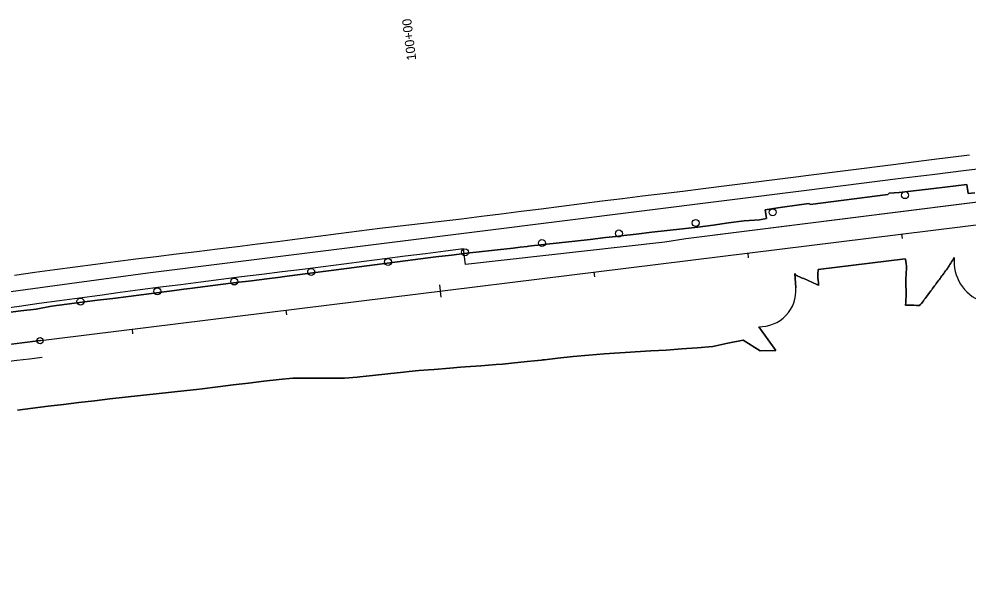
# Model space of a CAD drawing. Extents: x 1568809 to 1572786, y 728326 to 734907.
# Drawn here: x 1570015 to 1570627, y 731986 to 732358 of the extents above; entities that cross this region are included whole.
import ezdxf

# ---------------------------------------------------------------- set-up
doc = ezdxf.new("R2010")
doc.units = 0
for name, color, linetype in [('R_Horz Alg', 7, 'Continuous'), ('R_Horz Alg Annot', 7, 'Continuous'), ('R_MOT', 7, 'Continuous'), ('R_No Plot', 7, 'Continuous'), ('R_Proposed Const Limits_Fill', 7, 'Continuous'), ('R_Striping', 7, 'Continuous')]:
    doc.layers.add(name, color=color, linetype=linetype)

msp = doc.modelspace()

# ---------------------------------------------------------------- linework, layer by layer
at = {"layer": 'R_Horz Alg'}
msp.add_line((1569774.69, 732119.01), (1571082.41, 732280.73), dxfattribs=at)
msp.add_arc((1570379.97, 729307.25), 2864.79, 97.05, 102.33591, dxfattribs=at)
at = {"layer": 'R_Horz Alg Annot'}
msp.add_line((1569897.12, 732134.15), (1570028.36, 732150.38), dxfattribs=at)
for points in [[(1570584.5, 732216.13), (1570584.13, 732219.11)], [(1570485.25, 732203.86), (1570484.88, 732206.84)], [(1570386.01, 732191.59), (1570385.64, 732194.56)], [(1570285.91, 732186.26), (1570286.89, 732178.32)], [(1570187.52, 732167.04), (1570187.15, 732170.02)], [(1570088.28, 732154.77), (1570087.91, 732157.74)]]:
    msp.add_lwpolyline(points, dxfattribs=at)
msp.add_circle((1570028.36, 732150.38), 2, dxfattribs=at)
at = {"layer": 'R_MOT'}
for centre in [(1570586.12, 732244.2), (1570500.72, 732233.17), (1570451.19, 732226.24), (1570401.63, 732219.47), (1570352, 732213.28), (1570302.37, 732207.36), (1570252.77, 732201.07), (1570203.17, 732194.71), (1570153.56, 732188.5), (1570103.96, 732182.17), (1570054.42, 732175.57)]:
    msp.add_circle(centre, 2.25, dxfattribs=at)
at = {"layer": 'R_No Plot'}
for p, q in [((1570625.95, 732250.99), (1570626.75, 732245.23)), ((1570626.75, 732245.23), (1570625.95, 732250.99)), ((1570496.73, 732229.18), (1570495.95, 732234.82)), ((1570495.95, 732234.82), (1570496.73, 732229.18)), ((1570302.77, 732199.43), (1570301.51, 732209.57)), ((1570302.77, 732199.43), (1570301.51, 732209.57)), ((1570586.31, 732203.09), (1570530.21, 732196.15)), ((1570530.21, 732196.15), (1570586.31, 732203.09)), ((1570515.16, 732193.67), (1570515.78, 732184.45)), ((1570515.78, 732184.45), (1570515.16, 732193.67)), ((1570491.78, 732159.29), (1570502.74, 732143.97)), ((1570502.74, 732143.97), (1570491.78, 732159.29))]:
    msp.add_line(p, q, dxfattribs=at)
for points in [[(1571080.52, 732296.05), (1570444.72, 732215.92), (1570431.22, 732213.94), (1570302.77, 732199.43)], [(1571080.52, 732296.05), (1570973.02, 732293.44), (1570943.63, 732289.39), (1570933.75, 732279.73), (1570896.54, 732272.86), (1570444.72, 732215.92), (1570431.22, 732213.94), (1570302.77, 732199.43)], [(1570524.31, 732238.82), (1570524.95, 732238.13), (1570574.94, 732244.65), (1570575.94, 732245.46)], [(1570575.94, 732245.46), (1570574.94, 732244.65), (1570524.95, 732238.13), (1570524.31, 732238.82)], [(1570575.94, 732245.46), (1570582.24, 732245.98), (1570604.61, 732248.54), (1570625.95, 732250.99)], [(1570625.95, 732250.99), (1570604.61, 732248.54), (1570582.24, 732245.98), (1570575.94, 732245.46)], [(1570626.75, 732245.23), (1570631.21, 732245.78)], [(1570631.21, 732245.78), (1570626.75, 732245.23)], [(1570495.95, 732234.82), (1570504.17, 732235.97), (1570519.32, 732238.1), (1570524.31, 732238.82)], [(1570524.31, 732238.82), (1570519.32, 732238.1), (1570504.17, 732235.97), (1570495.95, 732234.82)], [(1570005.99, 732168.34), (1570015.92, 732169.51), (1570025.85, 732170.67), (1570035.69, 732172.64), (1570045.61, 732173.86), (1570055.53, 732175.11), (1570065.45, 732176.38), (1570075.37, 732177.64), (1570085.29, 732178.92), (1570095.21, 732180.22), (1570105.13, 732181.48), (1570115.05, 732182.74), (1570121.14, 732183.54), (1570124.96, 732184.05), (1570134.88, 732185.29), (1570144.8, 732186.57), (1570154.73, 732187.8), (1570164.65, 732189.03), (1570174.57, 732190.26), (1570183.36, 732191.36), (1570184.5, 732191.5), (1570194.42, 732192.73), (1570204.33, 732194.04), (1570214.25, 732195.35), (1570216.08, 732195.6), (1570224.16, 732196.65), (1570226, 732196.9), (1570234.08, 732197.96), (1570243.99, 732199.27), (1570253.91, 732200.56), (1570263.83, 732201.85), (1570273.74, 732203.15), (1570283.66, 732204.45), (1570293.59, 732205.59), (1570303.53, 732206.73), (1570313.47, 732207.83), (1570317.43, 732208.28), (1570323.41, 732208.94), (1570333.34, 732210.07), (1570337.9, 732210.58), (1570342.55, 732211.11), (1570343.28, 732211.19), (1570353.22, 732212.32), (1570363.15, 732213.44), (1570373.1, 732214.53), (1570383.03, 732215.66), (1570392.97, 732216.79), (1570399.78, 732217.56), (1570402.91, 732217.91), (1570412.84, 732219.08), (1570422.77, 732220.22), (1570432.71, 732221.35), (1570442.65, 732222.48), (1570452.58, 732223.59), (1570462.51, 732224.81), (1570472.39, 732226.37), (1570482.32, 732227.56), (1570492.32, 732228.23), (1570496.73, 732229.18)], [(1570496.73, 732229.18), (1570492.32, 732228.23), (1570482.32, 732227.56), (1570472.39, 732226.37), (1570462.51, 732224.81), (1570452.58, 732223.59), (1570442.65, 732222.48), (1570432.71, 732221.35), (1570422.77, 732220.22), (1570412.84, 732219.08), (1570402.91, 732217.91), (1570399.78, 732217.56), (1570392.97, 732216.79), (1570383.03, 732215.66), (1570373.1, 732214.53), (1570363.15, 732213.44), (1570353.22, 732212.32), (1570343.28, 732211.19), (1570342.55, 732211.11), (1570337.9, 732210.58), (1570333.34, 732210.07), (1570323.41, 732208.94), (1570317.43, 732208.28), (1570313.47, 732207.83), (1570303.53, 732206.73), (1570293.59, 732205.59), (1570283.66, 732204.45), (1570273.74, 732203.15), (1570263.83, 732201.85), (1570253.91, 732200.56), (1570243.99, 732199.27), (1570234.08, 732197.96), (1570226, 732196.9), (1570224.16, 732196.65), (1570216.08, 732195.6), (1570214.25, 732195.35), (1570204.33, 732194.04), (1570194.42, 732192.73), (1570184.5, 732191.5), (1570183.36, 732191.36), (1570174.57, 732190.26), (1570164.65, 732189.03), (1570154.73, 732187.8), (1570144.8, 732186.57), (1570134.88, 732185.29), (1570124.96, 732184.05), (1570121.14, 732183.54), (1570115.05, 732182.74), (1570105.13, 732181.48), (1570095.21, 732180.22), (1570085.29, 732178.92), (1570075.37, 732177.64), (1570065.45, 732176.38), (1570055.53, 732175.11), (1570045.61, 732173.86), (1570035.69, 732172.64), (1570025.85, 732170.67), (1570015.92, 732169.51), (1570005.99, 732168.34)], [(1570301.51, 732209.57), (1570289.87, 732208.1), (1570276.82, 732206.44), (1570263.78, 732204.79), (1570250.74, 732203.13), (1570237.44, 732201.43), (1570224.14, 732199.72), (1570210.85, 732198.02), (1570197.55, 732196.32), (1570184.46, 732194.68), (1570171.36, 732193.05), (1570158.27, 732191.41), (1570145.18, 732189.78), (1570132.12, 732188.11), (1570119.06, 732186.43), (1570106, 732184.76), (1570092.95, 732183.09), (1570079.91, 732181.33), (1570066.88, 732179.57), (1570053.85, 732177.81), (1570040.82, 732176.05), (1570027.86, 732174.24), (1570014.9, 732172.44), (1570001.94, 732170.63)], [(1570301.51, 732209.57), (1570289.87, 732208.1), (1570276.82, 732206.44), (1570263.78, 732204.79), (1570250.74, 732203.13), (1570237.44, 732201.43), (1570224.14, 732199.72), (1570210.85, 732198.02), (1570197.55, 732196.32), (1570184.46, 732194.68), (1570171.36, 732193.05), (1570158.27, 732191.41), (1570145.18, 732189.78), (1570132.12, 732188.11), (1570119.06, 732186.43), (1570106, 732184.76), (1570092.95, 732183.09), (1570079.91, 732181.33), (1570066.88, 732179.57), (1570053.85, 732177.81), (1570040.82, 732176.05), (1570027.86, 732174.24), (1570014.9, 732172.44), (1570001.94, 732170.63)], [(1570586.45, 732173.28), (1570586.47, 732173.55), (1570586.56, 732174.75), (1570586.65, 732175.94), (1570586.74, 732177.14), (1570586.83, 732178.34), (1570586.92, 732179.53), (1570586.89, 732180.83), (1570586.84, 732182.13), (1570586.79, 732183.44), (1570586.74, 732184.75), (1570586.69, 732186.05), (1570586.65, 732187.36), (1570586.6, 732188.67), (1570586.6, 732189.93), (1570586.69, 732191.13), (1570586.78, 732192.33), (1570586.87, 732193.53), (1570586.96, 732194.73), (1570587.04, 732195.93), (1570587.13, 732197.12), (1570586.97, 732198.52), (1570586.77, 732199.95), (1570586.56, 732201.38), (1570586.35, 732202.81), (1570586.31, 732203.09)], [(1570586.31, 732203.09), (1570586.35, 732202.81), (1570586.56, 732201.38), (1570586.77, 732199.95), (1570586.97, 732198.52), (1570587.13, 732197.12), (1570587.04, 732195.93), (1570586.96, 732194.73), (1570586.87, 732193.53), (1570586.78, 732192.33), (1570586.69, 732191.13), (1570586.6, 732189.93), (1570586.6, 732188.67), (1570586.65, 732187.36), (1570586.69, 732186.05), (1570586.74, 732184.75), (1570586.79, 732183.44), (1570586.84, 732182.13), (1570586.89, 732180.83), (1570586.92, 732179.53), (1570586.83, 732178.34), (1570586.74, 732177.14), (1570586.65, 732175.94), (1570586.56, 732174.75), (1570586.47, 732173.55), (1570586.45, 732173.28)], [(1570617.86, 732203.94), (1570616.67, 732201.99), (1570616.15, 732201.13), (1570615.62, 732200.27), (1570615.1, 732199.41), (1570614.58, 732198.55), (1570614.04, 732197.7), (1570613.44, 732196.9), (1570612.85, 732196.09), (1570612.25, 732195.29), (1570611.66, 732194.48), (1570611.07, 732193.68), (1570610.47, 732192.87), (1570609.88, 732192.07), (1570609.28, 732191.26), (1570608.69, 732190.46), (1570608.09, 732189.66), (1570607.5, 732188.85), (1570606.9, 732188.05), (1570606.31, 732187.24), (1570605.72, 732186.44), (1570605.12, 732185.63), (1570604.52, 732184.83), (1570603.93, 732184.03), (1570603.33, 732183.22), (1570602.73, 732182.42), (1570602.14, 732181.62), (1570601.54, 732180.82), (1570600.94, 732180.01), (1570600.35, 732179.21), (1570599.76, 732178.4), (1570599.16, 732177.6), (1570598.57, 732176.79), (1570597.98, 732175.98), (1570597.39, 732175.18), (1570596.79, 732174.37), (1570596.2, 732173.57), (1570595.21, 732173.07), (1570593.54, 732173.11), (1570591.86, 732173.15), (1570590.18, 732173.19), (1570588.51, 732173.23), (1570586.83, 732173.27), (1570586.45, 732173.28)], [(1570586.45, 732173.28), (1570586.83, 732173.27), (1570588.51, 732173.23), (1570590.18, 732173.19), (1570591.86, 732173.15), (1570593.54, 732173.11), (1570595.21, 732173.07), (1570596.2, 732173.57), (1570596.79, 732174.37), (1570597.39, 732175.18), (1570597.98, 732175.98), (1570598.57, 732176.79), (1570599.16, 732177.6), (1570599.76, 732178.4), (1570600.35, 732179.21), (1570600.94, 732180.01), (1570601.54, 732180.82), (1570602.14, 732181.62), (1570602.73, 732182.42), (1570603.33, 732183.22), (1570603.93, 732184.03), (1570604.52, 732184.83), (1570605.12, 732185.63), (1570605.72, 732186.44), (1570606.31, 732187.24), (1570606.9, 732188.05), (1570607.5, 732188.85), (1570608.09, 732189.66), (1570608.69, 732190.46), (1570609.28, 732191.26), (1570609.88, 732192.07), (1570610.47, 732192.87), (1570611.07, 732193.68), (1570611.66, 732194.48), (1570612.25, 732195.29), (1570612.85, 732196.09), (1570613.44, 732196.9), (1570614.04, 732197.7), (1570614.58, 732198.55), (1570615.1, 732199.41), (1570615.62, 732200.27), (1570616.15, 732201.13), (1570616.67, 732201.99), (1570617.86, 732203.94)], [(1570530.21, 732196.15), (1570530.15, 732195.78), (1570529.84, 732193.74), (1570529.83, 732192.11), (1570529.97, 732190.66), (1570530.11, 732189.21), (1570530.24, 732187.76), (1570530.38, 732186.3), (1570530.4, 732186)], [(1570530.4, 732186), (1570530.38, 732186.3), (1570530.24, 732187.76), (1570530.11, 732189.21), (1570529.97, 732190.66), (1570529.83, 732192.11), (1570529.84, 732193.74), (1570530.15, 732195.78), (1570530.21, 732196.15)], [(1570530.4, 732186), (1570530.21, 732186.09), (1570529.27, 732186.51), (1570528.33, 732186.94), (1570527.4, 732187.36), (1570526.46, 732187.78), (1570525.52, 732188.21), (1570524.58, 732188.63), (1570523.65, 732189.06), (1570522.71, 732189.48), (1570521.77, 732189.9), (1570520.83, 732190.33), (1570519.9, 732190.75), (1570518.96, 732191.17), (1570518.02, 732191.6), (1570517.08, 732191.96), (1570516.78, 732192.08), (1570516.49, 732192.24), (1570516.21, 732192.43), (1570515.94, 732192.65), (1570515.68, 732192.9), (1570515.45, 732193.18), (1570515.25, 732193.49), (1570515.16, 732193.67)], [(1570515.16, 732193.67), (1570515.25, 732193.49), (1570515.45, 732193.18), (1570515.68, 732192.9), (1570515.94, 732192.65), (1570516.21, 732192.43), (1570516.49, 732192.24), (1570516.78, 732192.08), (1570517.08, 732191.96), (1570518.02, 732191.6), (1570518.96, 732191.17), (1570519.9, 732190.75), (1570520.83, 732190.33), (1570521.77, 732189.9), (1570522.71, 732189.48), (1570523.65, 732189.06), (1570524.58, 732188.63), (1570525.52, 732188.21), (1570526.46, 732187.78), (1570527.4, 732187.36), (1570528.33, 732186.94), (1570529.27, 732186.51), (1570530.21, 732186.09), (1570530.4, 732186)], [(1570502.74, 732143.97), (1570492.69, 732143.73), (1570481.76, 732150.66), (1570471.92, 732148.74), (1570462.1, 732146.65), (1570452.15, 732145.61), (1570442.15, 732144.99), (1570432.16, 732144.3), (1570422.16, 732143.71), (1570412.16, 732143.12), (1570409, 732142.94), (1570402.16, 732142.48), (1570392.16, 732141.82), (1570382.2, 732140.92), (1570372.23, 732140.04), (1570362.29, 732138.98), (1570353.68, 732138.06), (1570352.34, 732137.91), (1570351.61, 732137.84), (1570346.95, 732137.34), (1570342.4, 732136.85), (1570332.44, 732135.91), (1570326.46, 732135.27), (1570322.48, 732134.94), (1570312.5, 732134.19), (1570309.36, 732133.93), (1570302.52, 732133.42), (1570299.37, 732133.18), (1570292.53, 732132.66), (1570282.57, 732131.78), (1570278.92, 732131.51), (1570272.58, 732131.05), (1570266.46, 732130.4), (1570262.64, 732129.99), (1570252.69, 732128.93), (1570242.74, 732127.95), (1570234.63, 732127.1), (1570232.8, 732126.85), (1570224.67, 732126.14), (1570222.8, 732126.18), (1570212.72, 732126.23), (1570202.64, 732126.24), (1570192.57, 732126.23), (1570191.41, 732126.23), (1570182.61, 732125.29), (1570172.66, 732124.21), (1570162.74, 732123.03), (1570152.81, 732121.8), (1570142.89, 732120.58), (1570132.96, 732119.35), (1570129.13, 732118.94), (1570123.03, 732118.18), (1570113.08, 732117.13), (1570103.14, 732116.06), (1570093.2, 732115), (1570083.26, 732113.89), (1570073.32, 732112.77), (1570063.38, 732111.62), (1570053.45, 732110.45), (1570043.52, 732109.27), (1570033.6, 732108.05), (1570023.67, 732106.82), (1570013.75, 732105.61)], [(1570013.75, 732105.61), (1570023.67, 732106.82), (1570033.6, 732108.05), (1570043.52, 732109.27), (1570053.45, 732110.45), (1570063.38, 732111.62), (1570073.32, 732112.77), (1570083.26, 732113.89), (1570093.2, 732115), (1570103.14, 732116.06), (1570113.08, 732117.13), (1570123.03, 732118.18), (1570129.13, 732118.94), (1570132.96, 732119.35), (1570142.89, 732120.58), (1570152.81, 732121.8), (1570162.74, 732123.03), (1570172.66, 732124.21), (1570182.61, 732125.29), (1570191.41, 732126.23), (1570192.57, 732126.23), (1570202.64, 732126.24), (1570212.72, 732126.23), (1570222.8, 732126.18), (1570224.67, 732126.14), (1570232.8, 732126.85), (1570234.63, 732127.1), (1570242.74, 732127.95), (1570252.69, 732128.93), (1570262.64, 732129.99), (1570266.46, 732130.4), (1570272.58, 732131.05), (1570278.92, 732131.51), (1570282.57, 732131.78), (1570292.53, 732132.66), (1570299.37, 732133.18), (1570302.52, 732133.42), (1570309.36, 732133.93), (1570312.5, 732134.19), (1570322.48, 732134.94), (1570326.46, 732135.27), (1570332.44, 732135.91), (1570342.4, 732136.85), (1570346.95, 732137.34), (1570351.61, 732137.84), (1570352.34, 732137.91), (1570353.68, 732138.06), (1570362.29, 732138.98), (1570372.23, 732140.04), (1570382.2, 732140.92), (1570392.16, 732141.82), (1570402.16, 732142.48), (1570409, 732142.94), (1570412.16, 732143.12), (1570422.16, 732143.71), (1570432.16, 732144.3), (1570442.15, 732144.99), (1570452.15, 732145.61), (1570462.1, 732146.65), (1570471.92, 732148.74), (1570481.76, 732150.66), (1570492.69, 732143.73), (1570502.74, 732143.97)]]:
    msp.add_lwpolyline(points, dxfattribs=at)
for centre, radius, start, end in [((1570645.26, 732201.4), 27.52, 174.69779, 249.03334), ((1570645.26, 732201.4), 27.52, 174.69779, 249.03334), ((1570492.26, 732182.86), 23.57, 268.82799, 3.86307), ((1570492.26, 732182.86), 23.57, 268.82799, 3.86307)]:
    msp.add_arc(centre, radius, start, end, dxfattribs=at)
at = {"layer": 'R_Proposed Const Limits_Fill'}
msp.add_lwpolyline([(1570005.99, 732168.34), (1570015.92, 732169.51), (1570025.85, 732170.67), (1570035.69, 732172.64), (1570045.61, 732173.86), (1570055.53, 732175.11), (1570065.45, 732176.38), (1570075.37, 732177.64), (1570085.29, 732178.92), (1570095.21, 732180.22), (1570105.13, 732181.48), (1570115.05, 732182.74), (1570121.14, 732183.54), (1570124.96, 732184.05), (1570134.88, 732185.29), (1570144.8, 732186.57), (1570154.73, 732187.8), (1570164.65, 732189.03), (1570174.57, 732190.26), (1570183.36, 732191.36), (1570184.5, 732191.5), (1570194.42, 732192.73), (1570204.33, 732194.04), (1570214.25, 732195.35), (1570216.08, 732195.6), (1570224.16, 732196.65), (1570226, 732196.9), (1570234.08, 732197.96), (1570243.99, 732199.27), (1570253.91, 732200.56), (1570263.83, 732201.85), (1570273.74, 732203.15), (1570283.66, 732204.45), (1570293.59, 732205.59), (1570303.53, 732206.73), (1570313.47, 732207.83), (1570317.43, 732208.28), (1570323.41, 732208.94), (1570333.34, 732210.07), (1570337.9, 732210.58), (1570342.55, 732211.11), (1570343.28, 732211.19), (1570353.22, 732212.32), (1570363.15, 732213.44), (1570373.1, 732214.53), (1570383.03, 732215.66), (1570392.97, 732216.79), (1570399.78, 732217.56), (1570402.91, 732217.91), (1570412.84, 732219.08), (1570422.77, 732220.22), (1570432.71, 732221.35), (1570442.65, 732222.48), (1570452.58, 732223.59), (1570462.51, 732224.81), (1570472.39, 732226.37), (1570482.32, 732227.56), (1570492.32, 732228.23), (1570496.73, 732229.18)], dxfattribs=at)
at = {"layer": 'R_Striping'}
for points in [[(1570522.16, 732256.86), (1570578.58, 732264.01), (1570603.18, 732267.13), (1570627.78, 732270.25)], [(1570522.6, 732247.41), (1570581.64, 732254.94), (1570603.59, 732257.58), (1570625.54, 732260.22), (1570638.72, 732261.75)], [(1570011.89, 732192.66), (1570024.92, 732194.42), (1570037.94, 732196.19), (1570050.98, 732197.9), (1570064.01, 732199.61), (1570077.04, 732201.32), (1570090.08, 732203.03), (1570103.24, 732204.65), (1570116.39, 732206.26), (1570129.55, 732207.88), (1570142.71, 732209.5), (1570155.62, 732211.12), (1570168.52, 732212.75), (1570181.42, 732214.38), (1570194.32, 732216), (1570207.6, 732217.71), (1570220.87, 732219.42), (1570234.14, 732221.13), (1570247.42, 732222.84), (1570260.59, 732224.37), (1570273.76, 732225.9), (1570286.93, 732227.43), (1570300.1, 732228.96), (1570312.95, 732230.58), (1570325.8, 732232.2), (1570338.65, 732233.82), (1570351.5, 732235.44), (1570364.6, 732237.11), (1570377.7, 732238.78), (1570390.79, 732240.44), (1570403.89, 732242.11), (1570416.91, 732243.69), (1570429.92, 732245.27), (1570442.94, 732246.86), (1570455.96, 732248.44), (1570471.31, 732250.37), (1570486.67, 732252.3), (1570502.02, 732254.23), (1570517.38, 732256.16), (1570522.16, 732256.86)], [(1569091.81, 731985.64), (1569147.99, 731999.1), (1569330.25, 732041.98), (1569622.48, 732112.98), (1569698.68, 732129.84), (1569723.78, 732135.38), (1569804.21, 732150.59), (1569837.55, 732156.52), (1569935.04, 732171.96), (1570097.77, 732194.1), (1570522.6, 732247.41)]]:
    msp.add_lwpolyline(points, dxfattribs=at)
msp.add_arc((1570369.29, 729305.42), 2854.31, 96.83257, 102.11849, dxfattribs=at)

# ---------------------------------------------------------------- texts
at = {"layer": 'R_Horz Alg Annot'}
msp.add_text('100+00', height=6, rotation=97.05, dxfattribs=at).set_placement((1570270.96, 732331.52))

doc.saveas('drawing.dxf')
